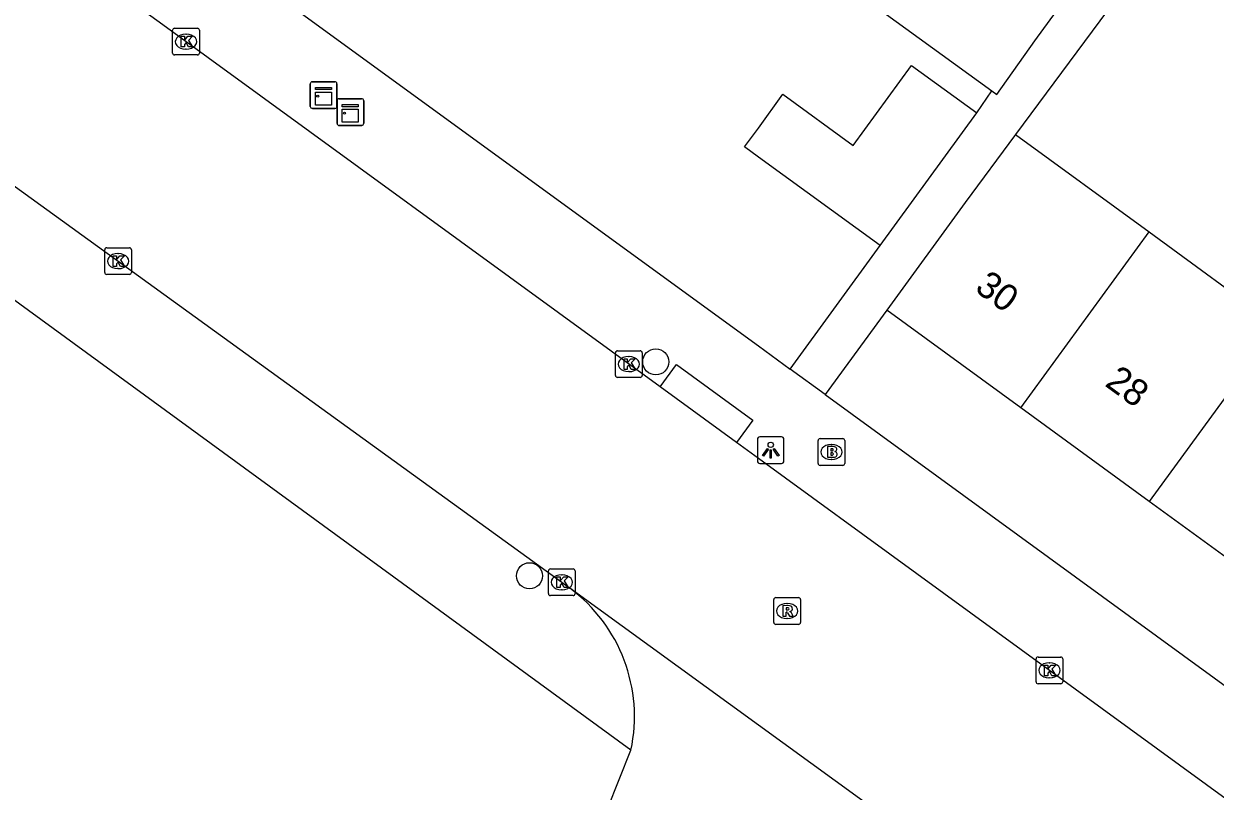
# Model space of a CAD drawing. Extents: x 159675 to 160530, y 382179 to 382901.
# Drawn here: x 159972.49 to 160017.11, y 382378.09 to 382406.84 of the extents above; entities that cross this region are included whole.
import ezdxf

# ---------------------------------------------------------------- set-up
doc = ezdxf.new("R2010")
doc.units = 0
for name, color, linetype in [('IMGEO_Boom', 7, 'Continuous'), ('IMGEO_Brandkraan', 7, 'Continuous'), ('IMGEO_Kast', 7, 'Continuous'), ('IMGEO_Kolk', 7, 'Continuous'), ('IMGEO_Lichtpunt', 7, 'Continuous'), ('IMGEO_Pand', 7, 'Continuous'), ('IMGEO_Pand_nummerreeks', 7, 'Continuous'), ('IMGEO_Rijbaan_lokaal_gesloten', 7, 'Continuous'), ('IMGEO_Rijbaan_lokaal_open', 7, 'Continuous'), ('IMGEO_Rioolput', 7, 'Continuous'), ('IMGEO_Voetpad_open', 7, 'Continuous')]:
    doc.layers.add(name, color=color, linetype=linetype)

msp = doc.modelspace()

# ---------------------------------------------------------------- linework, layer by layer
at = {"layer": 'IMGEO_Boom'}
for centre in [(159996.156, 382394.176), (159991.427, 382386.161)]:
    msp.add_circle(centre, 0.489, dxfattribs=at)
at = {"layer": 'IMGEO_Brandkraan'}
for p, q in [((160002.235, 382390.373), (160002.235, 382391.225)), ((160002.31, 382391.299), (160003.162, 382391.299)), ((160002.723, 382391.079), (160002.748, 382391.079)), ((160003.236, 382391.225), (160003.236, 382390.373)), ((160002.746, 382390.519), (160002.721, 382390.519)), ((160003.162, 382390.299), (160002.31, 382390.299))]:
    msp.add_line(p, q, dxfattribs=at)
for points in [[(160002.235, 382390.373), (160002.235, 382391.225)], [(160002.31, 382391.299), (160003.162, 382391.299)], [(160002.583, 382390.999), (160002.583, 382390.599), (160002.796, 382390.599)], [(160002.814, 382390.999), (160002.583, 382390.999)], [(160002.762, 382390.918), (160002.708, 382390.918), (160002.708, 382390.842)], [(160003.236, 382391.225), (160003.236, 382390.373)], [(160002.708, 382390.842), (160002.761, 382390.842)], [(160002.77, 382390.766), (160002.708, 382390.766), (160002.708, 382390.685)], [(160002.708, 382390.685), (160002.77, 382390.685)], [(160003.162, 382390.299), (160002.31, 382390.299)]]:
    msp.add_lwpolyline(points, dxfattribs=at)
for centre, radius, start, end in [((160002.312, 382391.223), 0.0765, 91.552, 178.448), ((160002.312, 382391.223), 0.0765, 91.552, 178.448), ((160002.763, 382390.88), 0.0379, 267.8285, 90.9355), ((160002.818, 382390.854), 0.145, 59.4692, 91.5367), ((160002.843, 382390.901), 0.0922, 285.5137, 58.1501), ((160003.16, 382391.223), 0.0765, 1.552, 88.448), ((160003.16, 382391.223), 0.0765, 1.552, 88.448), ((160002.771, 382390.725), 0.0404, 269.8759, 90.5077), ((160002.802, 382390.85), 0.251, 268.6676, 293.5347), ((160002.848, 382390.709), 0.105, 301.3115, 78.989), ((160002.312, 382390.375), 0.0765, 181.552, 268.448), ((160002.312, 382390.375), 0.0765, 181.552, 268.448), ((160003.16, 382390.375), 0.0765, 271.552, 358.448), ((160003.16, 382390.375), 0.0765, 271.552, 358.448)]:
    msp.add_arc(centre, radius, start, end, dxfattribs=at)
for centre, major_axis, ratio, start_param, end_param in [((160002.722, 382390.799), (-0.387, 0.002), 0.722429, 4.712389, 7.853982), ((160002.747, 382390.799), (-0.39, 0.002), 0.717154, 1.570796, 4.712389)]:
    msp.add_ellipse(centre, major_axis=major_axis, ratio=ratio, start_param=start_param, end_param=end_param, dxfattribs=at)
at = {"layer": 'IMGEO_Kast'}
for p, q in [((159983.216, 382403.746), (159983.216, 382404.587)), ((159983.216, 382404.587), (159983.216, 382403.746)), ((159983.291, 382404.671), (159984.132, 382404.671)), ((159984.132, 382404.671), (159983.291, 382404.671)), ((159984.216, 382404.596), (159984.216, 382403.755)), ((159984.216, 382403.755), (159984.216, 382404.596)), ((159984.218, 382403.107), (159984.218, 382403.948)), ((159984.218, 382403.948), (159984.218, 382403.107)), ((159984.293, 382404.032), (159985.134, 382404.032)), ((159985.134, 382404.032), (159984.293, 382404.032)), ((159985.218, 382403.957), (159985.218, 382403.116)), ((159985.218, 382403.116), (159985.218, 382403.957)), ((159984.141, 382403.671), (159983.3, 382403.671)), ((159983.3, 382403.671), (159984.141, 382403.671)), ((159985.143, 382403.032), (159984.302, 382403.032)), ((159984.302, 382403.032), (159985.143, 382403.032))]:
    msp.add_line(p, q, dxfattribs=at)
for points in [[(159983.411, 382404.461), (159984.011, 382404.461), (159984.011, 382404.376), (159983.411, 382404.376), (159983.411, 382404.461)], [(159983.411, 382404.286), (159984.011, 382404.286), (159984.011, 382403.797), (159983.411, 382403.797), (159983.411, 382404.286)], [(159984.413, 382403.822), (159985.013, 382403.822), (159985.013, 382403.737), (159984.413, 382403.737), (159984.413, 382403.822)], [(159984.413, 382403.647), (159985.013, 382403.647), (159985.013, 382403.158), (159984.413, 382403.158), (159984.413, 382403.647)]]:
    msp.add_lwpolyline(points, dxfattribs=at)
for centre in [(159983.495, 382404.135), (159984.497, 382403.496)]:
    msp.add_circle(centre, 0.0377, dxfattribs=at)
for centre, start, end in [((159983.294, 382404.593), 92.4484, 184.2845), ((159983.294, 382404.593), 92.4484, 184.2845), ((159984.138, 382404.593), 2.4484, 94.2845), ((159984.138, 382404.593), 2.4484, 94.2845), ((159984.296, 382403.954), 92.4484, 184.2845), ((159984.296, 382403.954), 92.4484, 184.2845), ((159985.14, 382403.954), 2.4484, 94.2845), ((159985.14, 382403.954), 2.4484, 94.2845), ((159983.294, 382403.749), 182.4484, 274.2845), ((159983.294, 382403.749), 182.4484, 274.2845), ((159984.138, 382403.749), 272.4484, 4.2845), ((159984.138, 382403.749), 272.4484, 4.2845), ((159984.296, 382403.11), 182.4484, 274.2845), ((159984.296, 382403.11), 182.4484, 274.2845), ((159985.14, 382403.11), 272.4484, 4.2845), ((159985.14, 382403.11), 272.4484, 4.2845)]:
    msp.add_arc(centre, 0.0779, start, end, dxfattribs=at)
at = {"layer": 'IMGEO_Kolk'}
for p, q in [((159978.062, 382405.747), (159978.062, 382406.599)), ((159978.137, 382406.673), (159978.989, 382406.673)), ((159979.063, 382406.599), (159979.063, 382405.747)), ((159978.55, 382406.453), (159978.575, 382406.453)), ((159978.989, 382405.673), (159978.137, 382405.673)), ((159978.573, 382405.893), (159978.548, 382405.893)), ((159975.516, 382397.524), (159975.516, 382398.376)), ((159975.591, 382398.45), (159976.443, 382398.45)), ((159976.004, 382398.23), (159976.029, 382398.23)), ((159976.517, 382398.376), (159976.517, 382397.524)), ((159976.027, 382397.67), (159976.002, 382397.67)), ((159976.443, 382397.45), (159975.591, 382397.45)), ((159994.646, 382393.665), (159994.646, 382394.517)), ((159994.721, 382394.591), (159995.573, 382394.591)), ((159995.647, 382394.517), (159995.647, 382393.665)), ((159995.134, 382394.371), (159995.159, 382394.371)), ((159995.573, 382393.591), (159994.721, 382393.591)), ((159995.157, 382393.811), (159995.132, 382393.811)), ((159992.135, 382385.492), (159992.135, 382386.344)), ((159992.21, 382386.418), (159993.062, 382386.418)), ((159992.623, 382386.198), (159992.648, 382386.198)), ((159993.136, 382386.344), (159993.136, 382385.492)), ((159992.646, 382385.638), (159992.621, 382385.638)), ((159993.062, 382385.418), (159992.21, 382385.418)), ((160010.397, 382382.192), (160010.397, 382383.044)), ((160010.472, 382383.118), (160011.324, 382383.118)), ((160010.885, 382382.898), (160010.91, 382382.898)), ((160011.398, 382383.044), (160011.398, 382382.192)), ((160011.324, 382382.118), (160010.472, 382382.118)), ((160010.908, 382382.338), (160010.883, 382382.338))]:
    msp.add_line(p, q, dxfattribs=at)
for points in [[(159978.062, 382405.747), (159978.062, 382406.599)], [(159978.137, 382406.673), (159978.989, 382406.673)], [(159979.063, 382406.599), (159979.063, 382405.747)], [(159978.383, 382406.373), (159978.506, 382406.373), (159978.506, 382406.222), (159978.636, 382406.373), (159978.8, 382406.373), (159978.654, 382406.222), (159978.807, 382405.973), (159978.655, 382405.973), (159978.57, 382406.137), (159978.506, 382406.07), (159978.506, 382405.973), (159978.383, 382405.973), (159978.383, 382406.373)], [(159978.989, 382405.673), (159978.137, 382405.673)], [(159975.516, 382397.524), (159975.516, 382398.376)], [(159975.591, 382398.45), (159976.443, 382398.45)], [(159975.837, 382398.15), (159975.96, 382398.15), (159975.96, 382397.999), (159976.09, 382398.15), (159976.254, 382398.15), (159976.108, 382397.999), (159976.261, 382397.75), (159976.109, 382397.75), (159976.024, 382397.914), (159975.96, 382397.847), (159975.96, 382397.75), (159975.837, 382397.75), (159975.837, 382398.15)], [(159976.517, 382398.376), (159976.517, 382397.524)], [(159976.443, 382397.45), (159975.591, 382397.45)], [(159994.646, 382393.665), (159994.646, 382394.517)], [(159994.721, 382394.591), (159995.573, 382394.591)], [(159995.647, 382394.517), (159995.647, 382393.665)], [(159994.967, 382394.291), (159995.09, 382394.291), (159995.09, 382394.14), (159995.22, 382394.291), (159995.384, 382394.291), (159995.238, 382394.14), (159995.391, 382393.891), (159995.239, 382393.891), (159995.154, 382394.055), (159995.09, 382393.988), (159995.09, 382393.891), (159994.967, 382393.891), (159994.967, 382394.291)], [(159995.573, 382393.591), (159994.721, 382393.591)], [(159992.135, 382385.492), (159992.135, 382386.344)], [(159992.21, 382386.418), (159993.062, 382386.418)], [(159992.456, 382386.118), (159992.579, 382386.118), (159992.579, 382385.967), (159992.709, 382386.118), (159992.873, 382386.118), (159992.727, 382385.967), (159992.88, 382385.718), (159992.728, 382385.718), (159992.643, 382385.882), (159992.579, 382385.815), (159992.579, 382385.718), (159992.456, 382385.718), (159992.456, 382386.118)], [(159993.136, 382386.344), (159993.136, 382385.492)], [(159993.062, 382385.418), (159992.21, 382385.418)], [(160010.397, 382382.192), (160010.397, 382383.044)], [(160010.472, 382383.118), (160011.324, 382383.118)], [(160011.398, 382383.044), (160011.398, 382382.192)], [(160010.718, 382382.818), (160010.841, 382382.818), (160010.841, 382382.667), (160010.971, 382382.818), (160011.135, 382382.818), (160010.989, 382382.667), (160011.142, 382382.418), (160010.99, 382382.418), (160010.905, 382382.582), (160010.841, 382382.515), (160010.841, 382382.418), (160010.718, 382382.418), (160010.718, 382382.818)], [(160011.324, 382382.118), (160010.472, 382382.118)]]:
    msp.add_lwpolyline(points, dxfattribs=at)
for centre, start, end in [((159978.139, 382406.597), 91.552, 178.448), ((159978.139, 382406.597), 91.552, 178.448), ((159978.987, 382406.597), 1.552, 88.448), ((159978.987, 382406.597), 1.552, 88.448), ((159978.139, 382405.749), 181.552, 268.448), ((159978.139, 382405.749), 181.552, 268.448), ((159978.987, 382405.749), 271.552, 358.448), ((159978.987, 382405.749), 271.552, 358.448), ((159975.593, 382398.374), 91.552, 178.448), ((159975.593, 382398.374), 91.552, 178.448), ((159976.441, 382398.374), 1.552, 88.448), ((159976.441, 382398.374), 1.552, 88.448), ((159975.593, 382397.526), 181.552, 268.448), ((159975.593, 382397.526), 181.552, 268.448), ((159976.441, 382397.526), 271.552, 358.448), ((159976.441, 382397.526), 271.552, 358.448), ((159994.723, 382394.515), 91.552, 178.448), ((159994.723, 382394.515), 91.552, 178.448), ((159995.571, 382394.515), 1.552, 88.448), ((159995.571, 382394.515), 1.552, 88.448), ((159994.723, 382393.667), 181.552, 268.448), ((159994.723, 382393.667), 181.552, 268.448), ((159995.571, 382393.667), 271.552, 358.448), ((159995.571, 382393.667), 271.552, 358.448), ((159992.212, 382386.342), 91.552, 178.448), ((159992.212, 382386.342), 91.552, 178.448), ((159993.06, 382386.342), 1.552, 88.448), ((159993.06, 382386.342), 1.552, 88.448), ((159992.212, 382385.494), 181.552, 268.448), ((159992.212, 382385.494), 181.552, 268.448), ((159993.06, 382385.494), 271.552, 358.448), ((159993.06, 382385.494), 271.552, 358.448), ((160010.474, 382383.042), 91.552, 178.448), ((160010.474, 382383.042), 91.552, 178.448), ((160011.322, 382383.042), 1.552, 88.448), ((160011.322, 382383.042), 1.552, 88.448), ((160010.474, 382382.194), 181.552, 268.448), ((160010.474, 382382.194), 181.552, 268.448), ((160011.322, 382382.194), 271.552, 358.448), ((160011.322, 382382.194), 271.552, 358.448)]:
    msp.add_arc(centre, 0.0765, start, end, dxfattribs=at)
for centre, major_axis, ratio, start_param, end_param in [((159978.549, 382406.173), (-0.387, 0.002), 0.722429, 4.712389, 7.853982), ((159978.574, 382406.173), (-0.39, 0.002), 0.717154, 1.570796, 4.712389), ((159976.003, 382397.95), (-0.387, 0.002), 0.722429, 4.712389, 7.853982), ((159976.028, 382397.95), (-0.39, 0.002), 0.717154, 1.570796, 4.712389), ((159995.133, 382394.091), (-0.387, 0.002), 0.722429, 4.712389, 7.853982), ((159995.158, 382394.091), (-0.39, 0.002), 0.717154, 1.570796, 4.712389), ((159992.622, 382385.918), (-0.387, 0.002), 0.722429, 4.712389, 7.853982), ((159992.647, 382385.918), (-0.39, 0.002), 0.717154, 1.570796, 4.712389), ((160010.884, 382382.618), (-0.387, 0.002), 0.722429, 4.712389, 7.853982), ((160010.909, 382382.618), (-0.39, 0.002), 0.717154, 1.570796, 4.712389)]:
    msp.add_ellipse(centre, major_axis=major_axis, ratio=ratio, start_param=start_param, end_param=end_param, dxfattribs=at)
at = {"layer": 'IMGEO_Lichtpunt'}
for p, q in [((160000.863, 382391.365), (160000.055, 382391.365)), ((160000.863, 382391.365), (160000.055, 382391.365)), ((159999.961, 382391.27), (159999.961, 382390.463)), ((159999.961, 382391.27), (159999.961, 382390.463)), ((160000.957, 382390.463), (160000.957, 382391.27)), ((160000.957, 382390.463), (160000.957, 382391.27)), ((160000.055, 382390.369), (160000.863, 382390.369)), ((160000.055, 382390.369), (160000.863, 382390.369))]:
    msp.add_line(p, q, dxfattribs=at)
for points in [[(160000.335, 382390.934), (160000.374, 382390.906), (160000.186, 382390.644), (160000.148, 382390.671), (160000.335, 382390.934)], [(160000.437, 382390.886), (160000.484, 382390.886), (160000.484, 382390.564), (160000.437, 382390.564), (160000.437, 382390.886)], [(160000.547, 382390.906), (160000.585, 382390.933), (160000.772, 382390.671), (160000.733, 382390.643), (160000.547, 382390.906)]]:
    msp.add_lwpolyline(points, dxfattribs=at)
msp.add_circle((160000.46, 382391.068), 0.0994, dxfattribs=at)
for centre, start, end in [((160000.055, 382391.27), 90, 180), ((160000.055, 382391.27), 90, 180), ((160000.863, 382391.27), 0, 90), ((160000.863, 382391.27), 0, 90), ((160000.055, 382390.463), 180, 270), ((160000.055, 382390.463), 180, 270), ((160000.863, 382390.463), 270, 0), ((160000.863, 382390.463), 270, 360)]:
    msp.add_arc(centre, 0.0946, start, end, dxfattribs=at)
at = {"layer": 'IMGEO_Pand'}
for points in [[(160011.718, 382408.628), (160006.758, 382412.221), (160004.279, 382408.799), (160005.25, 382408.095), (160004.664, 382407.285), (160008.748, 382404.326)], [(160008.748, 382404.326), (160008.928, 382404.196), (160010.355, 382406.208), (160011.973, 382408.444), (160011.718, 382408.628)], [(160004.555, 382398.53), (160000, 382401.849), (159999.482, 382402.226), (160000, 382402.937), (160000.92, 382404.2), (160003.553, 382402.281), (160005.738, 382405.28), (160008.178, 382403.501)], [(160004.555, 382398.53), (160008.178, 382403.501)], [(160009.634, 382402.696), (160007.75, 382400.151), (160004.805, 382396.109)], [(160009.634, 382402.696), (160014.631, 382399.046)], [(160009.826, 382392.451), (160014.631, 382399.046)], [(160014.631, 382399.046), (160019.438, 382395.527)], [(160009.826, 382392.451), (160004.805, 382396.109)], [(160019.438, 382395.527), (160014.641, 382388.943)], [(160014.641, 382388.943), (160009.826, 382392.451)], [(160019.577, 382385.347), (160014.641, 382388.943)]]:
    msp.add_lwpolyline(points, dxfattribs=at)
at = {"layer": 'IMGEO_Rijbaan_lokaal_gesloten'}
for points in [[(159996.317, 382393.238), (159977.556, 382406.905), (159976.539, 382407.646)], [(159969.32, 382402.798), (159992.637, 382385.919), (159992.936, 382385.697)], [(159999.175, 382391.156), (159996.317, 382393.238)], [(160078.11, 382333.649), (160000, 382390.554), (159999.175, 382391.156)], [(160006.662, 382375.729), (160000, 382380.567), (159992.936, 382385.697)]]:
    msp.add_lwpolyline(points, dxfattribs=at)
at = {"layer": 'IMGEO_Rijbaan_lokaal_open'}
msp.add_lwpolyline([(159992.155, 382374.522), (159994.35, 382377.434), (159995.228, 382379.629)], dxfattribs=at)
msp.add_arc((159989.368, 382380.883), 5.992, 347.9248, 53.4602, dxfattribs=at)
at = {"layer": 'IMGEO_Rioolput'}
for p, q in [((160000.577, 382384.416), (160000.577, 382385.268)), ((160000.652, 382385.342), (160001.504, 382385.342)), ((160001.065, 382385.122), (160001.09, 382385.122)), ((160001.578, 382385.268), (160001.578, 382384.416)), ((160001.504, 382384.342), (160000.652, 382384.342)), ((160001.088, 382384.562), (160001.063, 382384.562))]:
    msp.add_line(p, q, dxfattribs=at)
for points in [[(160000.577, 382384.416), (160000.577, 382385.268)], [(160000.652, 382385.342), (160001.504, 382385.342)], [(160001.578, 382385.268), (160001.578, 382384.416)], [(160001.166, 382385.04), (160000.914, 382385.042), (160000.914, 382384.642)], [(160000.914, 382384.642), (160001.038, 382384.642), (160001.038, 382384.804), (160001.049, 382384.804)], [(160001.092, 382384.961), (160001.038, 382384.961), (160001.038, 382384.88)], [(160001.038, 382384.88), (160001.09, 382384.88)], [(160001.096, 382384.775), (160001.167, 382384.642), (160001.307, 382384.642), (160001.242, 382384.768)], [(160001.504, 382384.342), (160000.652, 382384.342)]]:
    msp.add_lwpolyline(points, dxfattribs=at)
for centre, radius, start, end in [((160000.654, 382385.266), 0.0765, 91.552, 178.448), ((160000.654, 382385.266), 0.0765, 91.552, 178.448), ((160001.502, 382385.266), 0.0765, 1.552, 88.448), ((160001.502, 382385.266), 0.0765, 1.552, 88.448), ((160001.048, 382384.751), 0.0533, 26.0293, 88.6989), ((160001.074, 382385.069), 0.19, 274.7715, 282.9687), ((160001.098, 382384.865), 0.0964, 77.0061, 93.1865), ((160001.112, 382384.922), 0.0378, 276.6634, 79.6772), ((160001.165, 382384.93), 0.109, 350.3612, 89.416), ((160001.163, 382384.93), 0.112, 277.5842, 350.9817), ((160001.147, 382384.715), 0.108, 29.5134, 73.7905), ((160000.654, 382384.418), 0.0765, 181.552, 268.448), ((160000.654, 382384.418), 0.0765, 181.552, 268.448), ((160001.502, 382384.418), 0.0765, 271.552, 358.448), ((160001.502, 382384.418), 0.0765, 271.552, 358.448)]:
    msp.add_arc(centre, radius, start, end, dxfattribs=at)
for centre, major_axis, ratio, start_param, end_param in [((160001.064, 382384.842), (-0.387, 0.002), 0.722429, 4.712389, 7.853982), ((160001.089, 382384.842), (-0.39, 0.002), 0.717154, 1.570796, 4.712389)]:
    msp.add_ellipse(centre, major_axis=major_axis, ratio=ratio, start_param=start_param, end_param=end_param, dxfattribs=at)
at = {"layer": 'IMGEO_Voetpad_open'}
for points in [[(160020.653, 382411.499), (160017.707, 382413.601), (160009.634, 382402.696)], [(159979.733, 382409.536), (160000, 382394.771), (160001.186, 382393.907)], [(160008.178, 382403.501), (160008.748, 382404.326)], [(159995.228, 382379.629), (159967.191, 382400.081)], [(160001.186, 382393.907), (160004.555, 382398.53)], [(160004.805, 382396.109), (160002.502, 382392.948)], [(159996.317, 382393.238), (159996.929, 382394.079), (159999.787, 382391.997), (159999.175, 382391.156)], [(160002.502, 382392.948), (160001.186, 382393.907)], [(160002.502, 382392.948), (160051.264, 382357.423)]]:
    msp.add_lwpolyline(points, dxfattribs=at)

# ---------------------------------------------------------------- texts
at = {"layer": 'IMGEO_Pand_nummerreeks'}
for s, p in [('30', (160008.061, 382396.855)), ('28', (160012.937, 382393.302))]:
    msp.add_text(s, height=1, rotation=323.9266, dxfattribs=at).set_placement(p)

doc.saveas('drawing.dxf')
